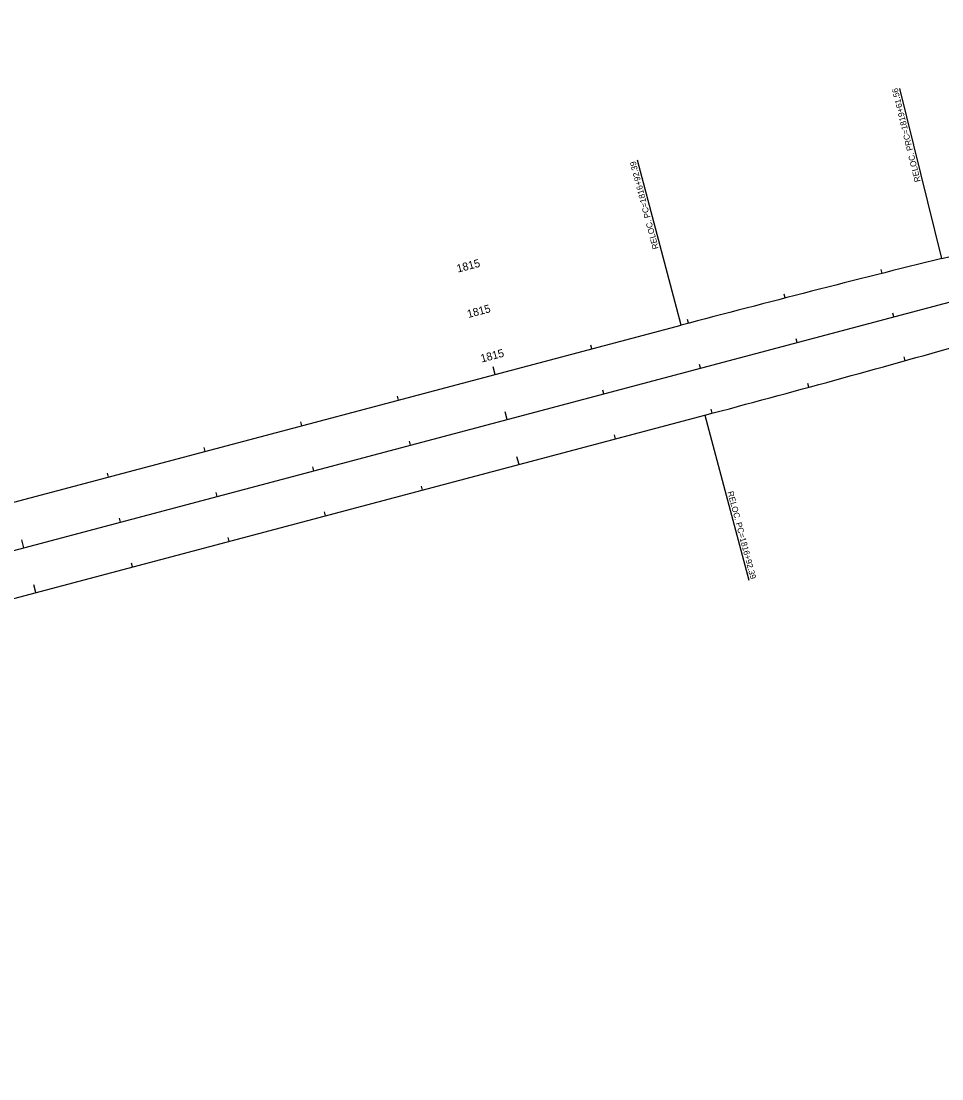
# Model space of a CAD drawing. Extents: x 2106154 to 2121963, y 864504 to 868517.
# Drawn here: x 2112089 to 2113010, y 867153 to 868210 of the extents above; entities that cross this region are included whole.
import ezdxf

# ---------------------------------------------------------------- set-up
doc = ezdxf.new("R2010")
doc.units = 0
for name, color, linetype in [('RD_HC_Cl', 7, 'Continuous'), ('RD_HC_CL_Rel', 7, 'Continuous'), ('RD_HC_Data_Rel', 7, 'Continuous'), ('RD_HC_Data_Tic', 7, 'Continuous'), ('RD_HC_Data_Tic_Rel', 7, 'Continuous'), ('RD_HC_TX_Rel_Sta50', 7, 'Continuous'), ('RD_HC_TX_Sta50', 7, 'Continuous')]:
    doc.layers.add(name, color=color, linetype=linetype)

msp = doc.modelspace()

# ---------------------------------------------------------------- linework, layer by layer
at = {"layer": 'RD_HC_Cl'}
msp.add_line((2110088.7, 867152.7), (2114077.7, 868210), dxfattribs=at)
at = {"layer": 'RD_HC_CL_Rel'}
for p, q in [((2111091.8, 867466.7), (2112749.4, 867906.1)), ((2111115.6, 867376.8), (2112773.2, 867816.2))]:
    msp.add_line(p, q, dxfattribs=at)
for centre, start, end in [((2109146.1, 883602.3), 283.88688, 284.84478), ((2116874.3, 852343.4), 103.88688, 104.84478), ((2108648.4, 883378.8), 284.84478, 285.80269)]:
    msp.add_arc(centre, 16100, start, end, dxfattribs=at)
at = {"layer": 'RD_HC_Data_Rel'}
for p, q in [((2113010.2, 867972.8), (2112968.2, 868142.6)), ((2112749.4, 867906.1), (2112705.7, 868071.1)), ((2112773.2, 867816.2), (2112817, 867651.1))]:
    msp.add_line(p, q, dxfattribs=at)
at = {"layer": 'RD_HC_Data_Tic'}
for p, q in [((2112962, 867914.3), (2112961, 867918.2)), ((2112865.4, 867888.7), (2112864.3, 867892.5)), ((2112768.7, 867863.1), (2112767.7, 867866.9)), ((2112672, 867837.4), (2112671, 867841.3)), ((2112575.4, 867811.8), (2112573.3, 867819.6)), ((2112478.7, 867786.2), (2112477.7, 867790.1)), ((2112382.1, 867760.6), (2112381, 867764.4)), ((2112285.4, 867735), (2112284.4, 867738.8)), ((2112188.7, 867709.3), (2112187.7, 867713.2)), ((2112092.1, 867683.7), (2112090, 867691.5))]:
    msp.add_line(p, q, dxfattribs=at)
at = {"layer": 'RD_HC_Data_Tic_Rel'}
for p, q in [((2112950.4, 867957.9), (2112949.5, 867961.8)), ((2112853.5, 867933.3), (2112852.5, 867937.1)), ((2112756.8, 867908), (2112755.7, 867911.9)), ((2112660.1, 867882.4), (2112659.1, 867886.2)), ((2112973.6, 867870.6), (2112972.5, 867874.5)), ((2112563.4, 867856.8), (2112561.4, 867864.5)), ((2112877.2, 867844.1), (2112876.1, 867847.9)), ((2112466.8, 867831.1), (2112465.8, 867835)), ((2112780.6, 867818.1), (2112779.6, 867822)), ((2112370.1, 867805.5), (2112369.1, 867809.4)), ((2112683.9, 867792.5), (2112682.9, 867796.4)), ((2112273.5, 867779.9), (2112272.4, 867783.8)), ((2112587.3, 867766.9), (2112585.2, 867774.6)), ((2112176.8, 867754.3), (2112175.8, 867758.1)), ((2112490.6, 867741.2), (2112489.6, 867745.1)), ((2112393.9, 867715.6), (2112392.9, 867719.5)), ((2112297.3, 867690), (2112296.3, 867693.9)), ((2112200.6, 867664.4), (2112199.6, 867668.3)), ((2112104, 867638.8), (2112101.9, 867646.5))]:
    msp.add_line(p, q, dxfattribs=at)

# ---------------------------------------------------------------- texts
at = {"layer": 'RD_HC_Data_Rel'}
for s, rotation, p in [('RELOC. PRC=1819+61.56', 103.8869, (2112989, 868050)), ('RELOC. PC=1816+92.39', 104.8448, (2112727, 867982.9)), ('RELOC. PC=1816+92.39', 284.8448, (2112795.7, 867739.3))]:
    msp.add_text(s, height=6, rotation=rotation, dxfattribs=at).set_placement(p)
at = {"layer": 'RD_HC_TX_Rel_Sta50'}
for p in [(2112526.1, 867958.6), (2112550, 867868.7)]:
    msp.add_text('1815', height=8, rotation=14.8448, dxfattribs=at).set_placement(p)
at = {"layer": 'RD_HC_TX_Sta50'}
msp.add_text('1815', height=8, rotation=14.8448, dxfattribs=at).set_placement((2112536.5, 867913.2))

doc.saveas('drawing.dxf')
